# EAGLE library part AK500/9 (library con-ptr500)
CONNECTOR
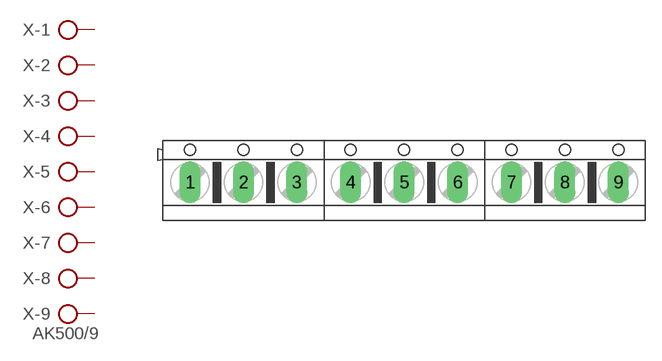
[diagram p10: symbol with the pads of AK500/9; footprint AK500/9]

Designator prefix X; gates -1=KL -2=KL -3=KL -4=KL -5=KL -6=KL -7=KL -8=KL -9=KLV

## AK500/9 (OC_FARNELL: unknown; OC_NEWARK: unknown)  [AK500/9]
1  -1:KL  pas
2  -2:KL  pas
3  -3:KL  pas
4  -4:KL  pas
5  -5:KL  pas
6  -6:KL  pas
7  -7:KL  pas
8  -8:KL  pas
9  -9:KL  pas

## Footprint AK500/9 (pad centres in mm)
CONNECTOR
drill 1.321 long: 1 -20.015,0; 2 -15.011,0; 3 -10.033,0; 4 -5.004,0; 5 0,0; 6 5.004,0; 7 10.033,0; 8 15.011,0; 9 20.015,0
